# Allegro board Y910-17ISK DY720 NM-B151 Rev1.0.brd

Outline 312 x 206.5 mm; copper layers: TOP, GND02, IN03, GND04, IN05, VCC06, VCC07, IN08, GND09, IN10, GND11, BOTTOM. Coordinates in mm from the lower left corner of the outline.
Outline path: 8.78,91.9 15,91.9 arc(18.3,88.6) 15,85.3 8.78,85.3 arc(5.48,88.6) 8.78,91.9 ; 129.73,82.69 129.73,82.68 129.75,82.68 arc(129.88,82.67) 130,82.68 131.42,82.68 arc(132.06,82.87) 132.34,83.47 arc(132.1,84.05) 131.52,84.27 129.91,84.27 arc(129.08,83.56) 129.73,82.69 ; 130.17,69.48 arc(129.28,70.24) 130.1,71.07 131.74,71.07 arc(132.33,70.85) 132.57,70.27 arc(132.31,69.68) 131.68,69.48 130.17,69.48

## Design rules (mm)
constraint set DEFAULT: min track width 0.097
net group 1.05G_FB: nets 1.05G_FB N33525142
net group 1.05VP_FB: nets 1.05VP_FB N23054269
net group 2.5VP_FB: nets 2.5VP_FB N20137254
net group +V_CPU_VREF_CA: nets +V_CPU_VREF_CA N19687681
net group +V_CPU_VREF_DQ_CHB: nets +V_CPU_VREF_DQ_CHB N19686618
net group AMP_SPK_L+: nets AMP_SPK_L+ N17011867
net group CHG_TGR: nets CHG_TGR N28554284
net group CK_CPU_24M_: nets CK_CPU_24M_N CK_CPU_24M_P
net group CK_CPU_BCLK_: nets CK_CPU_BCLK_N CK_CPU_BCLK_P
net group CK_CPU_PCIBCLK_: nets CK_CPU_PCIBCLK_N CK_CPU_PCIBCLK_P
net group CK_CR_: nets CK_CR_N CK_CR_P
net group CK_LAN: nets N16819243 N16819245
net group CK_LAN_: nets CK_LAN_N CK_LAN_P
net group CK_PCIE_SSD1_: nets CK_PCIE_SSD1_N CK_PCIE_SSD1_P
net group CK_PCIE_SSD2_: nets CK_PCIE_SSD2_N CK_PCIE_SSD2_P
net group CK_PEG1_: nets CK_PEG1_N CK_PEG1_P
net group CK_TBT: nets CK_TBT_N CK_TBT_P
net group CK_WLAN_: nets CK_WLAN_N CK_WLAN_P
net group CK_XDP_: nets CK_XDP_N CK_XDP_P
net group CSCOMP_1PH_A: nets CSCOMP_1PH_A CSSUM_1PH
net group CSCOMP_3PH_A: nets CSCOMP_3PH_A CSSUM_3PH_A
net group CSN1_3PH_A: nets CSN1_3PH_A CSP1_3PH_A
net group CSN2_3PH_A: nets CSN2_3PH_A CSP2_3PH_A
net group CSN3_3PH_A: nets CSN3_3PH_A CSP3_3PH_A
net group CSN4_3PH_A: nets CSN4_3PH_A CSP4_3PH_A
net group CSN_1PH: nets CSN_1PH CSP_1PH
net group DDI1_AUX_D: nets DDI1_AUX_DN DDI1_AUX_DP
net group DDI1_AUX_OUT_D: nets DDI1_AUX_OUT_DN DDI1_AUX_OUT_DP
net group DDI1_DN0: nets DDI1_DN0 N16691099
net group DDI1_DN1: nets DDI1_DN1 N16691187
net group DDI1_DN2: nets DDI1_DN2 N16691301
net group DDI1_DN3: nets DDI1_DN3 N16691365
net group DDI1_DP0: nets DDI1_DP0 N16691093
net group DDI1_DP1: nets DDI1_DP1 N16691181
net group DDI1_DP2: nets DDI1_DP2 N16691295
net group DDI1_DP3: nets DDI1_DP3 N16691335
net group DDI2_AUX_OUT_D: nets DDI2_AUX_OUT_DN DDI2_AUX_OUT_DP
net group DDI2_DN0: nets DDI2_DN0 N16694179
net group DDI2_DN1: nets DDI2_DN1 N16694223
net group DDI2_DN2: nets DDI2_DN2 N16694291
net group DDI2_DN3: nets DDI2_DN3 N16694359
net group DDI2_DP0: nets DDI2_DP0 N16694173
net group DDI2_DP1: nets DDI2_DP1 N16694217
net group DDI2_DP2: nets DDI2_DP2 N16694285
net group DDI2_DP3: nets DDI2_DP3 N16694353
net group DDI_AUX: nets DDI2_AUX_DN DDI2_AUX_DP
net group DIFFPAIR25: nets N16694397 N16694403
net group DIFFPAIR26: nets N35290569 N35290577
net group DIFFPAIR27: nets N35290550 N35290561
net group DIFFPAIR28: nets N34625001 N34625004
net group DMI_IT_MR_0_D: nets DMI_IT_MR_0_DN DMI_IT_MR_0_DP
net group DMI_IT_MR_1_D: nets DMI_IT_MR_1_DN DMI_IT_MR_1_DP
net group DMI_IT_MR_2_D: nets DMI_IT_MR_2_DN DMI_IT_MR_2_DP
net group DMI_IT_MR_3_D: nets DMI_IT_MR_3_DN DMI_IT_MR_3_DP
net group DMI_MT_IR_0_D: nets DMI_MT_IR_0_DN DMI_MT_IR_0_DP
net group DMI_MT_IR_1_D: nets DMI_MT_IR_1_DN DMI_MT_IR_1_DP
net group DMI_MT_IR_2_D: nets DMI_MT_IR_2_DN DMI_MT_IR_2_DP
net group DMI_MT_IR_3_D: nets DMI_MT_IR_3_DN DMI_MT_IR_3_DP
net group DP_AUX_C_DP_SCL: nets DP_AUX_C_DN_SDA DP_AUX_C_DP_SCL
net group DP_AUX_OUT_DP: nets DP_AUX_OUT_DN_SDA DP_AUX_OUT_DP_SCL
net group DP_TX0_C_DN: nets DP_TX0_C_DN DP_TX0_OUT_DN
net group DP_TX0_C_DP: nets DP_TX0_C_DP DP_TX0_OUT_DP
net group DP_TX1_C_DN: nets DP_TX1_C_DN DP_TX1_OUT_DN
net group DP_TX1_C_DP: nets DP_TX1_C_DP DP_TX1_OUT_DP
net group DP_TX2_C_DN: nets DP_TX2_C_DN DP_TX2_OUT_DN
net group DP_TX2_C_DP: nets DP_TX2_C_DP DP_TX2_OUT_DP
net group DP_TX3_C_DN: nets DP_TX3_C_DN DP_TX3_OUT_DN
net group DP_TX3_C_DP: nets DP_TX3_C_DP DP_TX3_OUT_DP
net group DPA_AUX_DN_C: nets DPA_AUX_DN_C GPU_DPA_AUX_DN_SDA
net group DPA_AUX_DP_C: nets DPA_AUX_DP_C GPU_DPA_AUX_DP_SCL
net group DPA_TX0_DN_C: nets DPA_TX0_DN_C GPU_DPA_TX0_DN
net group DPA_TX0_DP_C: nets DPA_TX0_DP_C GPU_DPA_TX0_DP
net group DPA_TX1_DN_C: nets DPA_TX1_DN_C GPU_DPA_TX1_DN
net group DPA_TX1_DP_C: nets DPA_TX1_DP_C GPU_DPA_TX1_DP
net group DPA_TX2_DN_C: nets DPA_TX2_DN_C GPU_DPA_TX2_DN
net group DPA_TX2_DP_C: nets DPA_TX2_DP_C GPU_DPA_TX2_DP
net group DPA_TX3_DN_C: nets DPA_TX3_DN_C GPU_DPA_TX3_DN
net group DPA_TX3_DP_C: nets DPA_TX3_DP_C GPU_DPA_TX3_DP
net group DPE_AUX_D_C: nets DPE_AUX_DN_C DPE_AUX_DP_C
net group DPE_TX0_D_C: nets DPE_TX0_DN_C DPE_TX0_DP_C
net group DPE_TX1_D_C: nets DPE_TX1_DN_C DPE_TX1_DP_C
net group DPE_TX2_D_C: nets DPE_TX2_DN_C DPE_TX2_DP_C
net group DPE_TX3_D_C: nets DPE_TX3_DN_C DPE_TX3_DP_C
net group DPF_AUX_D_C: nets DPF_AUX_DN_C DPF_AUX_DP_C
net group DPF_TX0_D_C: nets DPF_TX0_DN_C DPF_TX0_DP_C
net group DPF_TX1_D_C: nets DPF_TX1_DN_C DPF_TX1_DP_C
net group DPF_TX2_D_C: nets DPF_TX2_DN_C DPF_TX2_DP_C
net group DPF_TX3_D_C: nets DPF_TX3_DN_C DPF_TX3_DP_C
net group EDP_AUX_C_DN: nets EDP_AUX_C_DN GPU_EDP_AUX_DN
net group EDP_AUX_C_DP: nets EDP_AUX_C_DP GPU_EDP_AUX_DP
net group EDP_TX0_C_DN: nets EDP_TX0_C_DN GPU_EDP_TX0_DN
net group EDP_TX0_C_DP: nets EDP_TX0_C_DP GPU_EDP_TX0_DP
net group EDP_TX1_C_DN: nets EDP_TX1_C_DN GPU_EDP_TX1_DN
net group EDP_TX1_C_DP: nets EDP_TX1_C_DP GPU_EDP_TX1_DP
net group FBA_CLK: nets CLKA0_N CLKA1_N
net group FBC_CLK: nets CLKC0 CLKC0_N
net group FBD_WCK: nets FBD_WCK23 FBD_WCK23_N
net group GPU_DPA_SCL: nets GPU_DPA_SCL GPU_DPA_SDA
net group GPU_DPE_AUX_DN_SDA-SCL: nets GPU_DPE_AUX_DN_SDA GPU_DPE_AUX_DP_SCL
net group GPU_DPE_TX1: nets GPU_DPE_TX1_DN GPU_DPE_TX1_DP
net group GPU_DPE_TX2: nets GPU_DPE_TX2_DN GPU_DPE_TX2_DP
net group GPU_DPE_TX3: nets GPU_DPE_TX3_DN GPU_DPE_TX3_DP
net group GPU_DPF_AUX: nets GPU_DPF_AUX_DN GPU_DPF_AUX_DP
net group GPU_DPF_TX0: nets GPU_DPF_TX0_DN GPU_DPF_TX0_DP
net group GPU_DPF_TX1: nets GPU_DPF_TX1_DN GPU_DPF_TX1_DP
net group GPU_DPF_TX2: nets GPU_DPF_TX2_DN GPU_DPF_TX2_DP
net group GPU_DPF_TX3: nets GPU_DPF_TX3_DN GPU_DPF_TX3_DP
net group GPU_HDMI_CLK_DN: nets GPU_HDMI_CLK_DN N36820474
net group GPU_HDMI_CLK_DP: nets GPU_HDMI_CLK_DP N36820476
net group GPU_HDMI_DATA0_DN: nets GPU_HDMI_DATA0_DN N36820470
net group GPU_HDMI_DATA0_DP: nets GPU_HDMI_DATA0_DP N36820472
net group GPU_HDMI_DATA1_DN: nets GPU_HDMI_DATA1_DN N36820468
net group GPU_HDMI_DATA1_DP: nets GPU_HDMI_DATA1_DP N36820466
net group GPU_HDMI_DATA2_DN: nets GPU_HDMI_DATA2_DN N36820462
net group GPU_HDMI_DATA2_DP: nets GPU_HDMI_DATA2_DP N36820464
net group GPU_HDMI_DDC_CLK: nets GPU_HDMI_DDC_CLK GPU_HDMI_DDC_DATA
net group HDMI_CLK_D: nets HDMI_CLK_DN HDMI_CLK_DP
net group HDMI_CLK_R_D: nets HDMI_CLK_R_DN HDMI_CLK_R_DP
net group HDMI_CLK_RS_D: nets HDMI_CLK_RS_DN HDMI_CLK_RS_DP
net group HDMI_DATA0_D: nets HDMI_DATA0_DN HDMI_DATA0_DP
net group HDMI_DATA0_R_D: nets HDMI_DATA0_R_DN HDMI_DATA0_R_DP
net group HDMI_DATA0_RS_D: nets HDMI_DATA0_RS_DN HDMI_DATA0_RS_DP
net group HDMI_DATA1_D: nets HDMI_DATA1_DN HDMI_DATA1_DP
net group HDMI_DATA1_R_D: nets HDMI_DATA1_R_DN HDMI_DATA1_R_DP
net group HDMI_DATA1_RS_D: nets HDMI_DATA1_RS_DN HDMI_DATA1_RS_DP
net group HDMI_DATA2_D: nets HDMI_DATA2_DN HDMI_DATA2_DP
net group HDMI_DATA2_R_D: nets HDMI_DATA2_R_DN HDMI_DATA2_R_DP
net group HDMI_DATA2_RS_D: nets HDMI_DATA2_RS_DN HDMI_DATA2_RS_DP
net group HDMI_DDC_CLK: nets HDMI_DDC_CLK HDMI_DDC_DATA
net group HDMI_DDC_CLK_R: nets HDMI_DDC_CLK_R HDMI_DDC_DATA_R
net group MDI_0: nets MDI_N0 MDI_P0
net group MDI_1: nets MDI_N1 MDI_P1
net group MDI_2: nets MDI_N2 MDI_P2
net group MDI_3: nets MDI_N3 MDI_P3
net group MDO_0: nets MDO_N0 MDO_P0
net group MDO_1: nets MDO_N1 MDO_P1
net group MDO_2: nets MDO_N2 MDO_P2
net group MDO_3: nets MDO_N3 MDO_P3
net group N16977173: nets N16977173 N16977182
net group N16977185: nets N16977185 N16977188
net group N17009645: nets N17009645 N17009647
net group N17009677: nets N17009677 N17009679
net group N17009783: nets N17009783 N17009785
net group N17791490: nets N17791490 N17791569
net group N28554029: nets N28554029 N28554039
net group N28555679: nets N28555679 N28555719
net group PC_BEEP: nets N16980185 PC_BEEP
net group PCIE1_TBT_RX_DN0: nets N16693435 PCIE1_TBT_RX_DN0
net group PCIE1_TBT_RX_DP0: nets N16693389 PCIE1_TBT_RX_DP0
net group PCIE1_TBT_TX_DN0: nets N16691949 PCIE1_TBT_TX_DN0
net group PCIE1_TBT_TX_DP0: nets N16691909 PCIE1_TBT_TX_DP0
net group PCIE2_TBT_RX_DN1: nets N16693593 PCIE2_TBT_RX_DN1
net group PCIE2_TBT_RX_DP1: nets N16693587 PCIE2_TBT_RX_DP1
net group PCIE2_TBT_TX_DN1: nets N16691945 PCIE2_TBT_TX_DN1
net group PCIE2_TBT_TX_DP1: nets N16691941 PCIE2_TBT_TX_DP1
net group PCIE3_TBT_RX_DN2: nets N16693677 PCIE3_TBT_RX_DN2
net group PCIE3_TBT_RX_DP2: nets N16693655 PCIE3_TBT_RX_DP2
net group PCIE3_TBT_TX_DN2: nets N16693835 PCIE3_TBT_TX_DN2
net group PCIE3_TBT_TX_DP2: nets N16693791 PCIE3_TBT_TX_DP2
net group PCIE4_TBT_RX_DN3: nets N16693769 PCIE4_TBT_RX_DN3
net group PCIE4_TBT_RX_DP3: nets N16693763 PCIE4_TBT_RX_DP3
net group PCIE4_TBT_TX_DN3: nets N16693831 PCIE4_TBT_TX_DN3
net group PCIE4_TBT_TX_DP3: nets N16693827 PCIE4_TBT_TX_DP3
net group PCIE9_SSD2_RX_D0: nets PCIE9_SSD2_RX_DN0 PCIE9_SSD2_RX_DP0
net group PCIE9_SSD2_RX_R_D0: nets PCIE9_SSD2_RX_R_DN0 PCIE9_SSD2_RX_R_DP0
net group PCIE9_SSD2_TX_DN0: nets PCIE9_SSD2_TX_C_DN0 PCIE9_SSD2_TX_DN0
net group PCIE9_SSD2_TX_DP0: nets PCIE9_SSD2_TX_C_DP0 PCIE9_SSD2_TX_DP0
net group PCIE10_SSD2_RX_D1: nets PCIE10_SSD2_RX_DN1 PCIE10_SSD2_RX_DP1
net group PCIE10_SSD2_TX_DN1: nets PCIE10_SSD2_TX_C_DN1 PCIE10_SSD2_TX_DN1
net group PCIE10_SSD2_TX_DP1: nets PCIE10_SSD2_TX_C_DP1 PCIE10_SSD2_TX_DP1
net group PCIE11_SSD2_RX_D2: nets PCIE11_SSD2_RX_DN2 PCIE11_SSD2_RX_DP2
net group PCIE11_SSD2_TX_DN2: nets PCIE11_SSD2_TX_C_DN2 PCIE11_SSD2_TX_DN2
net group PCIE11_SSD2_TX_DP2: nets PCIE11_SSD2_TX_C_DP2 PCIE11_SSD2_TX_DP2
net group PCIE12_SSD2_RX_D3: nets PCIE12_SSD2_RX_DN3 PCIE12_SSD2_RX_DP3
net group PCIE12_SSD2_TX_DN3: nets PCIE12_SSD2_TX_C_DN3 PCIE12_SSD2_TX_DN3
net group PCIE12_SSD2_TX_DP3: nets PCIE12_SSD2_TX_C_DP3 PCIE12_SSD2_TX_DP3
net group PCIE13_SSD1_RX_D0: nets PCIE13_SSD1_RX_DN0 PCIE13_SSD1_RX_DP0
net group PCIE13_SSD1_TX_C_DN0: nets PCIE13_SSD1_TX_C_DN0 PCIE13_SSD1_TX_DN0
net group PCIE13_SSD1_TX_C_DP0: nets PCIE13_SSD1_TX_C_DP0 PCIE13_SSD1_TX_DP0
net group PCIE14_SSD1_RX_D1: nets PCIE14_SSD1_RX_DN1 PCIE14_SSD1_RX_DP1
net group PCIE14_SSD1_TX_C_DN1: nets PCIE14_SSD1_TX_C_DN1 PCIE14_SSD1_TX_DN1
net group PCIE14_SSD1_TX_C_DP1: nets PCIE14_SSD1_TX_C_DP1 PCIE14_SSD1_TX_DP1
net group PCIE15_SSD1_RX_D2: nets PCIE15_SSD1_RX_DN2 PCIE15_SSD1_RX_DP2
net group PCIE15_SSD1_TX_C_DN2: nets PCIE15_SSD1_TX_C_DN2 PCIE15_SSD1_TX_DN2
net group PCIE15_SSD1_TX_C_DP2: nets PCIE15_SSD1_TX_C_DP2 PCIE15_SSD1_TX_DP2
net group PCIE16_SSD1_RX_D3: nets PCIE16_SSD1_RX_DN3 PCIE16_SSD1_RX_DP3
net group PCIE16_SSD1_TX_C_DN3: nets PCIE16_SSD1_TX_C_DN3 PCIE16_SSD1_TX_DN3
net group PCIE16_SSD1_TX_C_DP3: nets PCIE16_SSD1_TX_C_DP3 PCIE16_SSD1_TX_DP3
net group PCIE_CR_RX_D: nets PCIE_CR_RX_DN PCIE_CR_RX_DP
net group PCIE_CR_TX_C_DN: nets PCIE_CR_TX_C_DN PCIE_CR_TX_DN
net group PCIE_CR_TX_C_DP: nets PCIE_CR_TX_C_DP PCIE_CR_TX_DP
net group PCIE_LAN_RX_C_DN: nets PCIE_LAN_RX_C_DN PCIE_LAN_RX_DN
net group PCIE_LAN_RX_C_DP: nets PCIE_LAN_RX_C_DP PCIE_LAN_RX_DP
net group PCIE_LAN_TX_C_DN: nets PCIE_LAN_TX_C_DN PCIE_LAN_TX_DN
net group PCIE_LAN_TX_C_DP: nets PCIE_LAN_TX_C_DP PCIE_LAN_TX_DP
net group PCIE_WLAN_RX_D: nets PCIE_WLAN_RX_DN PCIE_WLAN_RX_DP
net group PCIE_WLAN_TX_C_DN: nets PCIE_WLAN_TX_C_DN PCIE_WLAN_TX_DN
net group PCIE_WLAN_TX_C_DP: nets PCIE_WLAN_TX_C_DP PCIE_WLAN_TX_DP
net group PEG_PRX_C_GTX: nets PEG_PRX_C_GTX_N12 PEG_PRX_C_GTX_P12
net group PEG_PRX_C_GTX_N0: nets PEG_PRX_C_GTX_N0 PEG_PRX_GTX_N0
net group PEG_PRX_C_GTX_N1: nets PEG_PRX_C_GTX_N1 PEG_PRX_GTX_N1
net group PEG_PRX_C_GTX_N2: nets PEG_PRX_C_GTX_N2 PEG_PRX_GTX_N2
net group PEG_PRX_C_GTX_N3: nets PEG_PRX_C_GTX_N3 PEG_PRX_GTX_N3
net group PEG_PRX_C_GTX_N4: nets PEG_PRX_C_GTX_N4 PEG_PRX_GTX_N4
net group PEG_PRX_C_GTX_N5: nets PEG_PRX_C_GTX_N5 PEG_PRX_GTX_N5
net group PEG_PRX_C_GTX_N6: nets PEG_PRX_C_GTX_N6 PEG_PRX_GTX_N6
net group PEG_PRX_C_GTX_N7: nets PEG_PRX_C_GTX_N7 PEG_PRX_GTX_N7
net group PEG_PRX_C_GTX_P0: nets PEG_PRX_C_GTX_P0 PEG_PRX_GTX_P0
net group PEG_PRX_C_GTX_P1: nets PEG_PRX_C_GTX_P1 PEG_PRX_GTX_P1
net group PEG_PRX_C_GTX_P2: nets PEG_PRX_C_GTX_P2 PEG_PRX_GTX_P2
net group PEG_PRX_C_GTX_P3: nets PEG_PRX_C_GTX_P3 PEG_PRX_GTX_P3
net group PEG_PRX_C_GTX_P4: nets PEG_PRX_C_GTX_P4 PEG_PRX_GTX_P4
net group PEG_PRX_C_GTX_P5: nets PEG_PRX_C_GTX_P5 PEG_PRX_GTX_P5
net group PEG_PRX_C_GTX_P6: nets PEG_PRX_C_GTX_P6 PEG_PRX_GTX_P6
net group PEG_PRX_C_GTX_P7: nets PEG_PRX_C_GTX_P7 PEG_PRX_GTX_P7
net group PEG_PTX_C_GRX_N0: nets PEG_PTX_C_GRX_N0 PEG_PTX_GRX_N0
net group PEG_PTX_C_GRX_N1: nets PEG_PTX_C_GRX_N1 PEG_PTX_GRX_N1
net group PEG_PTX_C_GRX_N2: nets PEG_PTX_C_GRX_N2 PEG_PTX_GRX_N2
net group PEG_PTX_C_GRX_N3: nets PEG_PTX_C_GRX_N3 PEG_PTX_GRX_N3
net group PEG_PTX_C_GRX_N4: nets PEG_PTX_C_GRX_N4 PEG_PTX_GRX_N4
net group PEG_PTX_C_GRX_N5: nets PEG_PTX_C_GRX_N5 PEG_PTX_GRX_N5
net group PEG_PTX_C_GRX_N6: nets PEG_PTX_C_GRX_N6 PEG_PTX_GRX_N6
net group PEG_PTX_C_GRX_N7: nets PEG_PTX_C_GRX_N7 PEG_PTX_GRX_N7
net group PEG_PTX_C_GRX_N8: nets PEG_PTX_C_GRX_N8 PEG_PTX_GRX_N8
net group PEG_PTX_C_GRX_N9: nets PEG_PTX_C_GRX_N9 PEG_PTX_GRX_N9
net group PEG_PTX_C_GRX_N10: nets PEG_PTX_C_GRX_N10 PEG_PTX_GRX_N10
net group PEG_PTX_C_GRX_N11: nets PEG_PTX_C_GRX_N11 PEG_PTX_GRX_N11
net group PEG_PTX_C_GRX_N12: nets PEG_PTX_C_GRX_N12 PEG_PTX_GRX_N12
net group PEG_PTX_C_GRX_N13: nets PEG_PTX_C_GRX_N13 PEG_PTX_GRX_N13
net group PEG_PTX_C_GRX_N14: nets PEG_PTX_C_GRX_N14 PEG_PTX_GRX_N14
net group PEG_PTX_C_GRX_N15: nets PEG_PTX_C_GRX_N15 PEG_PTX_GRX_N15
net group PEG_PTX_C_GRX_P0: nets PEG_PTX_C_GRX_P0 PEG_PTX_GRX_P0
net group PEG_PTX_C_GRX_P1: nets PEG_PTX_C_GRX_P1 PEG_PTX_GRX_P1
net group PEG_PTX_C_GRX_P2: nets PEG_PTX_C_GRX_P2 PEG_PTX_GRX_P2
net group PEG_PTX_C_GRX_P3: nets PEG_PTX_C_GRX_P3 PEG_PTX_GRX_P3
net group PEG_PTX_C_GRX_P4: nets PEG_PTX_C_GRX_P4 PEG_PTX_GRX_P4
net group PEG_PTX_C_GRX_P5: nets PEG_PTX_C_GRX_P5 PEG_PTX_GRX_P5
net group PEG_PTX_C_GRX_P6: nets PEG_PTX_C_GRX_P6 PEG_PTX_GRX_P6
net group PEG_PTX_C_GRX_P7: nets PEG_PTX_C_GRX_P7 PEG_PTX_GRX_P7
net group PEG_PTX_C_GRX_P8: nets PEG_PTX_C_GRX_P8 PEG_PTX_GRX_P8
net group PEG_PTX_C_GRX_P9: nets PEG_PTX_C_GRX_P9 PEG_PTX_GRX_P9
net group PEG_PTX_C_GRX_P10: nets PEG_PTX_C_GRX_P10 PEG_PTX_GRX_P10
net group PEG_PTX_C_GRX_P11: nets PEG_PTX_C_GRX_P11 PEG_PTX_GRX_P11
net group PEG_PTX_C_GRX_P12: nets PEG_PTX_C_GRX_P12 PEG_PTX_GRX_P12
net group PEG_PTX_C_GRX_P13: nets PEG_PTX_C_GRX_P13 PEG_PTX_GRX_P13
net group PEG_PTX_C_GRX_P14: nets PEG_PTX_C_GRX_P14 PEG_PTX_GRX_P14
net group PEG_PTX_C_GRX_P15: nets PEG_PTX_C_GRX_P15 PEG_PTX_GRX_P15
net group REMOTE1_N: nets REMOTE1_N REMOTE1_P
net group REMOTE2_N: nets REMOTE2_N REMOTE2_P
net group SATA_RX__R_0: nets SATA_RX__R_N0 SATA_RX__R_P0
net group SATA_RX_C_DN0: nets SATA_RX_C_DN0 SATA_RX_DN0
net group SATA_RX_C_DP0: nets SATA_RX_C_DP0 SATA_RX_DP0
net group SATA_RX_C_N0: nets SATA_RX_C_N0 SATA_RX_N0
net group SATA_RX_C_P0: nets SATA_RX_C_P0 SATA_RX_P0
net group SATA_TX__R_0: nets SATA_TX__R_N0 SATA_TX__R_P0
net group SATA_TX_C_DN0: nets SATA_TX_C_DN0 SATA_TX_DN0
net group SATA_TX_C_DP0: nets SATA_TX_C_DP0 SATA_TX_DP0
net group SATA_TX_C_N0: nets SATA_TX_C_N0 SATA_TX_N0
net group SATA_TX_C_P0: nets SATA_TX_C_P0 SATA_TX_P0
net group SWF_R+: nets N17740217 SWF_R+
net group SWF_R-: nets N17740396 SWF_R-
net group SWF_RINN: nets SWF_RINN SWF_RINP
net group TBTA_DPSRC_AUX_N: nets N16694693 TBTA_DPSRC_AUX_N
net group TBTA_DPSRC_AUX_P: nets N16694687 TBTA_DPSRC_AUX_P
net group TBTA_RX0: nets TBTA_RX0_N TBTA_RX0_P
net group TBTA_RX1: nets TBTA_RX1_N TBTA_RX1_P
net group TBTA_TX0_N: nets N16695201 TBTA_TX0_N
net group TBTA_TX0_P: nets N16695207 TBTA_TX0_P
net group TBTA_TX1_N: nets N16695077 TBTA_TX1_N
net group TBTA_TX1_P: nets N16695083 TBTA_TX1_P
net group TBTA_USB2_D: nets TBTA_USB2_D_N TBTA_USB2_D_P
net group TBTA_USB2_P_B: nets TBTA_USB2_N_B TBTA_USB2_P_B
net group TBTA_USB2_P_T: nets TBTA_USB2_N_T TBTA_USB2_P_T
net group TBTB_RX0: nets TBTB_RX0_N TBTB_RX0_P
net group TBTB_RX0_N: nets TBTB_RX0_N_R TBTB_RX0_P_R
net group TBTB_TX0: nets TBTB_TX0_N TBTB_TX0_P
net group TBTB_TX0_: nets TBTB_TX0_N_R TBTB_TX0_P_R
net group TBTB_USB2_D: nets TBTB_USB2_D_N TBTB_USB2_D_P
net group TBTB_USB2_D__R: nets TBTB_USB2_D_N_R TBTB_USB2_D_P_R
net group USB2_CHG_PN: nets USB2_CHG_PN_R USB2_CHG_PP_R
net group USB2_CHG_PP: nets USB2_CHG_PN USB2_CHG_PP
net group USB2_D1: nets USB2_DN1 USB2_DP1
net group USB2_D2: nets USB2_DN2 USB2_DP2
net group USB2_D4: nets USB2_DN4 USB2_DP4
net group USB2_D4_R: nets USB2_DN4_R USB2_DP4_R
net group USB2_D5: nets USB2_DN5 USB2_DP5
net group USB2_D6: nets USB2_DN6 USB2_DP6
net group USB3_RX_D1: nets USB3_RX_DN1 USB3_RX_DP1
net group USB3_RX_D3: nets USB3_RX_DN3 USB3_RX_DP3
net group USB3_RX_D3_R: nets USB3_RX_DN3_R USB3_RX_DP3_R
net group USB3_RX_D6: nets USB3_RX_DN6 USB3_RX_DP6
net group USB3_TX_D1: nets USB3_TX_DN1 USB3_TX_DP1
net group USB3_TX_D3: nets USB3_TX_DN3 USB3_TX_DP3
net group USB3_TX_D3_C: nets USB3_TX_DN3_C USB3_TX_DP3_C
net group USB3_TX_D3_R: nets USB3_TX_DN3_R USB3_TX_DP3_R
net group USB3_TX_D6: nets USB3_TX_DN6 USB3_TX_DP6
net group USB3_TX_D6_C: nets USB3_TX_DN6_C USB3_TX_DP6_C
net group 8: nets HDA_SPKR HDA_SYNC SERIRQ
net group 10: nets SPK_L+ SPK_L- SPK_R+ SPK_R-
net group 15: nets DMIC_DATA H_PM_SYNC PCH_JTAG_TCK PCH_JTAG_TMS SUSCLK
net group 18: nets H_PECI
net group 20: nets DMIC_CLK DMIC_CLK_R HP_OUTL HP_OUTR
net group +3VLP_EC_AVCC: nets +3VLP_EC_AVCC
net group ADIN_1: nets N28551818
net group AMP_SPK_L-: nets AMP_SPK_L-
net group AMP_SPK_R+: nets N17011679
net group DP1: nets FBB_WCK01
net group DP2: nets CLKA0
net group DP3: nets CLKA1
net group DP11: nets FBB_WCK45
net group DP12: nets FBB_WCK67
net group DP21: nets FBA_WCK01
net group DP22: nets FBA_WCK23
net group DP24: nets FBA_WCK67
net group FBA_CMD: nets CMDA0 CMDA1 CMDA2 CMDA3 CMDA4 CMDA5 CMDA6 CMDA7 CMDA8 CMDA9 CMDA10 CMDA11 CMDA12 CMDA13 CMDA14 CMDA15 CMDA16 CMDA17 CMDA18 CMDA19 CMDA20 CMDA21 CMDA22 CMDA23 CMDA24 CMDA25 CMDA26 CMDA27 CMDA28 CMDA29 CMDA30 CMDA31
net group FBA_D0: nets DQMA0 DQSA0 MDA0 MDA1 MDA2 MDA3 MDA4 MDA5 MDA6 MDA7
net group FBA_D1: nets DQMA1 DQSA1 MDA8 MDA9 MDA10 MDA11 MDA12 MDA13 MDA14 MDA15
net group FBA_D2: nets DQMA2 DQSA2 MDA16 MDA17 MDA18 MDA19 MDA20 MDA21 MDA22 MDA23
net group FBA_D3: nets DQMA3 DQSA3 MDA24 MDA25 MDA26 MDA27 MDA28 MDA29 MDA30 MDA31
net group FBA_D4: nets DQMA4 DQSA4 MDA32 MDA33 MDA34 MDA35 MDA36 MDA37 MDA38 MDA39
net group FBA_D5: nets DQMA5 DQSA5 MDA40 MDA41 MDA42 MDA43 MDA44 MDA45 MDA46 MDA47
net group FBA_D6: nets DQMA6 DQSA6 MDA48 MDA49 MDA50 MDA51 MDA52 MDA53 MDA54 MDA55
net group FBA_D7: nets DQMA7 DQSA7 MDA56 MDA57 MDA58 MDA59 MDA60 MDA61 MDA62 MDA63
net group FBA_WCK: nets FBA_WCK01_N FBA_WCK23_N FBA_WCK67_N
net group FBB_CLK: nets CLKB0 CLKB0_N CLKB1 CLKB1_N
net group FBB_CMD: nets CMDB0 CMDB1 CMDB2 CMDB3 CMDB4 CMDB5 CMDB6 CMDB7 CMDB8 CMDB9 CMDB10 CMDB11 CMDB12 CMDB13 CMDB14 CMDB15 CMDB16 CMDB17 CMDB18 CMDB19 CMDB20 CMDB21 CMDB22 CMDB23 CMDB24 CMDB25 CMDB26 CMDB27 CMDB28 CMDB29 CMDB30 CMDB31
net group FBB_D0: nets DQMB0 DQSB0 MDB0 MDB1 MDB2 MDB3 MDB4 MDB5 MDB6 MDB7
net group FBB_D1: nets DQMB1 DQSB1 MDB8 MDB9 MDB10 MDB11 MDB12 MDB13 MDB14 MDB15
net group FBB_D2: nets DQMB2 DQSB2 MDB16 MDB17 MDB18 MDB19 MDB20 MDB21 MDB22 MDB23
net group FBB_D3: nets DQMB3 DQSB3 MDB24 MDB25 MDB26 MDB27 MDB28 MDB29 MDB30 MDB31
net group FBB_D4: nets DQMB4 DQSB4 MDB32 MDB33 MDB34 MDB35 MDB36 MDB37 MDB38 MDB39
net group FBB_D5: nets DQMB5 DQSB5 MDB40 MDB41 MDB42 MDB43 MDB44 MDB45 MDB46 MDB47
net group FBB_D6: nets DQMB6 DQSB6 MDB48 MDB49 MDB50 MDB51 MDB52 MDB53 MDB54 MDB55
net group FBB_D7: nets DQMB7 DQSB7 MDB56 MDB57 MDB58 MDB59 MDB60 MDB61 MDB62 MDB63
net group FBB_WCK: nets FBB_WCK01_N FBB_WCK45_N FBB_WCK67_N
net group FBC_CMD: nets CMDC0 CMDC1 CMDC2 CMDC3 CMDC4 CMDC5 CMDC6 CMDC7 CMDC8 CMDC9 CMDC10 CMDC11 CMDC12 CMDC13 CMDC14 CMDC15 CMDC16 CMDC17 CMDC18 CMDC19 CMDC20 CMDC21 CMDC22 CMDC23 CMDC24 CMDC25 CMDC26 CMDC27 CMDC28 CMDC29 CMDC30 CMDC31
net group FBC_D0: nets DQMC0 DQSC0 MDC0 MDC1 MDC2 MDC3 MDC4 MDC5 MDC6 MDC7
net group FBC_D1: nets DQMC1 DQSC1 MDC8 MDC9 MDC10 MDC11 MDC12 MDC13 MDC14 MDC15
net group FBC_D2: nets DQMC2 DQSC2 MDC16 MDC17 MDC18 MDC19 MDC20 MDC21 MDC22 MDC23
net group FBC_D3: nets DQMC3 DQSC3 MDC24 MDC25 MDC26 MDC27 MDC28 MDC29 MDC30 MDC31
net group FBC_D4: nets DQMC4 DQSC4 MDC32 MDC33 MDC34 MDC35 MDC36 MDC37 MDC38 MDC39
net group FBC_D5: nets DQMC5 DQSC5 MDC40 MDC41 MDC42 MDC43 MDC44 MDC45 MDC46 MDC47
net group FBC_D6: nets DQMC6 DQSC6 MDC48 MDC49 MDC50 MDC51 MDC52 MDC53 MDC54 MDC55
net group FBC_D7: nets DQMC7 DQSC7 MDC56 MDC57 MDC58 MDC59 MDC60 MDC61 MDC62 MDC63
net group FBC_WCK: nets FBC_WCK01 FBC_WCK01_N FBC_WCK23 FBC_WCK23_N FBC_WCK67 FBC_WCK67_N
net group FBD_CLK: nets CLKD0 CLKD0_N CLKD1 CLKD1_N
net group FBD_CMD: nets CMDD0 CMDD1 CMDD2 CMDD3 CMDD4 CMDD5 CMDD6 CMDD7 CMDD8 CMDD9 CMDD10 CMDD11 CMDD12 CMDD13 CMDD14 CMDD15 CMDD16 CMDD17 CMDD18 CMDD19 CMDD20 CMDD21 CMDD22 CMDD23 CMDD24 CMDD25 CMDD26 CMDD27 CMDD28 CMDD29 CMDD30 CMDD31
net group FBD_D0: nets DQMD0 DQSD0 MDD0 MDD1 MDD2 MDD3 MDD4 MDD5 MDD6 MDD7
net group FBD_D1: nets DQMD1 DQSD1 MDD8 MDD9 MDD10 MDD11 MDD12 MDD13 MDD14 MDD15
net group FBD_D2: nets DQMD2 DQSD2 MDD16 MDD17 MDD18 MDD19 MDD20 MDD21 MDD22 MDD23
net group FBD_D3: nets DQMD3 DQSD3 MDD24 MDD25 MDD26 MDD27 MDD28 MDD29 MDD30 MDD31
net group FBD_D4: nets DQMD4 DQSD4 MDD32 MDD33 MDD34 MDD35 MDD36 MDD37 MDD38 MDD39
net group FBD_D5: nets DQMD5 DQSD5 MDD40 MDD41 MDD42 MDD43 MDD44 MDD45 MDD46 MDD47
net group FBD_D6: nets DQMD6 DQSD6 MDD48 MDD49 MDD50 MDD51 MDD52 MDD53 MDD54 MDD55
net group FBD_D7: nets DQMD7 DQSD7 MDD56 MDD57 MDD58 MDD59 MDD60 MDD61 MDD62 MDD63
net group GPU_DPE_TX0: nets GPU_DPE_TX0_DN
net group N18288662: nets N18288662
net group NEAR TO PEG: nets +1.0V_VCCST_VCCSFR +1.0VALW +VCCSFR_OC DGPU_PEX_RST_N DGPU_PWROK GPU_DPE_TX0_DP GPU_EDP_BL_PWM_R H_THRMTRIP_N H_VCCST_PWRGD MAINON SUSON USB2_DN3
net group PEG: nets PEG_PRX_C_GTX_N8 PEG_PRX_C_GTX_N9 PEG_PRX_C_GTX_N10 PEG_PRX_C_GTX_N11 PEG_PRX_C_GTX_N13 PEG_PRX_C_GTX_N14 PEG_PRX_C_GTX_N15 PEG_PRX_C_GTX_P8 PEG_PRX_C_GTX_P9 PEG_PRX_C_GTX_P10 PEG_PRX_C_GTX_P11 PEG_PRX_C_GTX_P13 PEG_PRX_C_GTX_P14 PEG_PRX_C_GTX_P15 PEG_PRX_GTX_N8 PEG_PRX_GTX_N9 PEG_PRX_GTX_N10 PEG_PRX_GTX_N11 PEG_PRX_GTX_N12 PEG_PRX_GTX_N13 PEG_PRX_GTX_N14 PEG_PRX_GTX_N15 PEG_PRX_GTX_P8 PEG_PRX_GTX_P9 PEG_PRX_GTX_P10 PEG_PRX_GTX_P11 PEG_PRX_GTX_P12 PEG_PRX_GTX_P13 PEG_PRX_GTX_P14 PEG_PRX_GTX_P15
net group POWER: nets +3VALWP
net group PWR: nets +1.0V_VCCSFR +1.0V_VCCSTG_RC +1.2V_BST +1.2V_FB +1.2V_LG +1.2V_TON +1.2V_UGR +1.2VDDQ +1.05V_DGPU_PGOOD +1.8VA_AUD +1.8VALW_PCH +3V_1.8V_EC +3VA_AMP +3VALW_EC_FSPI +3VALW_LC_SPI +3VALW_SLG +3VALW_SPI +5V_KB_LED +5V_USB_KB +5VLDO +12V_SWF_BOOST +RTC_VCC +V3.3A_VCCPAZIO +V3.3A_VCCPGPPEF +V3.3A_VCCPGPPG +V3.3S_VCCATS +V_CPU_VREF_DQ_CHA +V_DIM_VREF_CA_CHA +V_DIM_VREF_CA_CHB +VBAT_EC +VCCAPLLEBB_1P0 +VCCAUSB_1P0_L +VCCDTS_1P0 +VCCDUSB_1P0 +VCCF100OC_1P0 +VCCFHV_2P8 +VCCPRTCPRIM_3P3 +VCCVDDQ_CLK +VSTBY0_EC +VTT_REFP
net group USB2_D3: nets USB2_DP3
net group XDP: nets XDP_TDI XDP_TDO XDP_TMS
nets with their own width: min track width 0.254; nets +1.8V_AON +1.8V_MAIN +1.55VSG +3V +CORE_PLLVDD_GPU +FB_PLL_AVDD +IFP_IOVDD +IFPAB_PLLVDD +IFPCD_PLLVDD +IFPEF_PLLVDD +PEX_VDD +VID_PLLVDD_GPU_1 +VID_PLLVDD_GPU_2 CFG_RCOMP FB_REFPLL_AVDD_GPU GND VDD18_GPU
nets with their own width: min track width 0.305; nets PEG_RCOMP
nets with their own width: min track width 0.381; nets +5VALW +NVVDDS +VGA_CORE
nets with their own width: min track width 1.016; nets CHASSIS1_GND
nets with their own width: min track width 1.524; nets B+

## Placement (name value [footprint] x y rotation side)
C1  -  [C_0402NEW]  199.56 154.51 180 bottom
C2  -  [C_0402NEW]  199.56 153.62 180 bottom
C3  -  [C_0402NEW]  197.58 151.97 180 bottom
C4  -  [C_0402NEW]  197.58 152.86 180 bottom
C5  -  [C_0402NEW]  199.44 150.45 180 bottom
C6  -  [C_0402NEW]  199.44 151.34 180 bottom
C7  -  [C_0402NEW]  202.99 149.05 180 bottom
C8  -  [C_0402NEW]  202.99 149.94 180 bottom
C9  -  [C_0402NEW]  199.49 148.03 180 bottom
C10  -  [C_0402NEW]  199.49 148.92 180 bottom
C11  -  [C_0402NEW]  202.92 147.12 180 bottom
C12  -  [C_0402NEW]  202.92 146.26 180 bottom
C13  -  [C_0402NEW]  199.49 145.62 180 bottom
C14  -  [C_0402NEW]  199.49 144.73 180 bottom
C15  -  [C_0402NEW]  202.92 142.95 180 bottom
C16  -  [C_0402NEW]  202.94 143.82 180 bottom
C17  -  [C_0402NEW]  199.44 141.68 180 bottom
C18  -  [C_0402NEW]  199.44 142.57 180 bottom
C19  -  [C_0402NEW]  202.99 140.29 180 bottom
C20  -  [C_0402NEW]  202.99 141.18 180 bottom
C21  -  [C_0402NEW]  199.44 139.27 180 bottom
C22  -  [C_0402NEW]  199.44 140.16 180 bottom
C23  -  [C_0402NEW]  202.99 137.62 180 bottom
C24  -  [C_0402NEW]  202.99 138.51 180 bottom
C25  -  [C_0402NEW]  199.44 137.62 180 bottom
C26  -  [C_0402NEW]  199.44 136.73 180 bottom
C27  -  [C_0402NEW]  202.99 134.95 180 bottom
C28  -  [C_0402NEW]  202.99 135.84 180 bottom
C29  -  [C_0402NEW]  199.44 134.19 180 bottom
C30  -  [C_0402NEW]  199.44 135.08 180 bottom
C31  -  [C_0402NEW]  202.99 132.29 180 bottom
C32  -  [C_0402NEW]  202.99 133.18 180 bottom
C33  -  [C_0402NEW]  148.69 152.43 270 top
C34  -  [C_B2]  222.83 159.46 0 top
C35  -  [C_0402NEW]  196.36 62.69 0 bottom
C36  -  [C_0402NEW]  197.28 63.58 180 bottom
C37  -  [C_0402NEW]  169.9 94.52 270 bottom
C38  -  [C_0402NEW]  167.23 93.6 90 bottom
C39  -  [C_B2]  121.23 61.67 0 top
C40  -  [C_0603NEW]  191.36 62.75 270 bottom
C41  -  [C_0603NEW]  175.86 62.75 270 bottom
C42  -  [C_0603NEW]  181.96 62.75 270 bottom
C43  -  [C_0603NEW]  168.37 62.75 270 bottom
C44  -  [C_0603NEW]  157.83 62.75 270 bottom
C45  -  [C_0603NEW]  185.01 62.75 270 bottom
C46  -  [C_0603NEW]  154.78 62.75 270 bottom
C47  -  [C_0603NEW]  166.97 62.75 270 bottom
C48  -  [C_0603NEW]  160.88 62.75 270 bottom
C49  -  [C_0603NEW]  163.93 62.75 270 bottom
C50  -  [C_0603NEW]  206.53 71.45 0 top
C51  -  [C_0603NEW]  206.53 69.17 0 top
C52  -  [C_0402NEW]  206.83 65.74 0 top
C53  -  [C_0402NEW]  206.78 77.04 0 top
C54  -  [C_0402NEW]  171.67 93.6 90 bottom
C55  -  [C_0402NEW]  150.46 62.51 270 bottom
C56  -  [C_0402NEW]  147.42 62.51 270 bottom
C57  -  [C_0402NEW]  165.7 62.51 270 bottom
C58  -  [C_0402NEW]  156.56 62.51 270 bottom
C59  -  [C_0402NEW]  162.66 62.51 270 bottom
C60  -  [C_0402NEW]  144.37 62.51 270 bottom
C61  -  [C_0402NEW]  172.82 62.51 270 bottom
C62  -  [C_0402NEW]  159.61 62.51 270 bottom
C63  -  [C_0402NEW]  153.51 62.51 270 bottom
C64  -  [C_0402NEW]  144.11 90.63 90 bottom
C65  -  [C_0603NEW]  206.66 70.44 0 bottom
C66  -  [C_0603NEW]  206.53 75.26 0 bottom
C67  -  [C_0402NEW]  206.78 76.41 0 bottom
C68  -  [C_0402NEW]  195.35 91.27 0 bottom
C69  -  [C_0402NEW]  196.26 93.04 180 bottom
C70  -  [C_0402NEW]  169.01 94.52 270 bottom
C71  -  [C_0402NEW]  31.41 44.15 180 bottom
C72  -  [C_B2]  120.98 96.85 0 top
C73  -  [C_0603NEW]  146.27 90.5 90 bottom
C74  -  [C_0603NEW]  155.42 90.38 90 bottom
C75  -  [C_0603NEW]  139.92 90.31 90 bottom
C76  -  [C_0603NEW]  174.21 91.27 90 bottom
C77  -  [C_0603NEW]  150.21 90.63 90 bottom
C78  -  [C_0603NEW]  160.24 90.44 90 bottom
C79  -  [C_0603NEW]  179.55 90.44 90 bottom
C80  -  [C_0603NEW]  185.01 90.38 90 bottom
C81  -  [C_0603NEW]  142.21 90.38 90 bottom
C82  -  [C_0603NEW]  162.53 90.5 90 bottom
C83  -  [C_0603NEW]  206.53 73.74 0 top
C84  -  [C_0603NEW]  206.53 79.2 0 top
C85  -  [C_0402NEW]  206.78 74.88 0 top
C86  -  [C_0402NEW]  206.78 72.6 0 top
C87  -  [C_B2]  231.64 161.75 180 top
C88  -  [C_0402NEW]  183.74 62.51 270 bottom
C89  -  [C_0402NEW]  177.64 62.51 270 bottom
C90  -  [C_0402NEW]  137.76 90.63 90 bottom
C91  -  [C_0402NEW]  141.07 90.63 90 bottom
C92  -  [C_0402NEW]  148.43 90.63 90 bottom
C93  -  [C_0402NEW]  195.04 62.51 270 bottom
C94  -  [C_0402NEW]  156.56 90.5 90 bottom
C95  -  [C_0402NEW]  194.15 62.51 270 bottom
C96  -  [C_0402NEW]  134.72 90.68 90 bottom
C97  -  [C_0402NEW]  138.78 90.63 90 bottom
C98  -  [C_0603NEW]  206.53 80.85 0 bottom
C99  -  [C_0603NEW]  206.53 78.34 0 bottom
C100  -  [C_0402NEW]  206.78 77.3 0 bottom
C101  -  [C_0402NEW]  196.36 60.91 0 bottom
C102  -  [C_0402NEW]  197.28 61.8 180 bottom
C103  -  [C_0402NEW]  171.67 59.72 270 bottom
C104  -  [C_0402NEW]  173.45 58.8 90 bottom
C105  -  [C_B2]  120.98 92.92 0 top
C106  -  [C_0603NEW]  164.94 90.38 90 bottom
C107  -  [C_0603NEW]  176.37 90.5 90 bottom
C108  -  [C_0603NEW]  188.44 90.38 90 bottom
C109  -  [C_0603NEW]  170.53 90.5 90 bottom
C110  -  [C_0603NEW]  136.24 90.63 90 bottom
C111  -  [C_0603NEW]  178.91 62.75 270 bottom
C112  -  [C_0603NEW]  182.34 90.25 90 bottom
C113  -  [C_0603NEW]  171.55 62.75 270 bottom
C114  -  [C_0603NEW]  192.76 90.38 90 bottom
C115  -  [C_0603NEW]  157.83 90.38 90 bottom
C116  -  [C_0603NEW]  206.53 66.88 0 top
C117  -  [C_0603NEW]  206.53 75.92 0 top
C118  -  [C_0402NEW]  206.78 68.02 0 top
C119  -  [C_0402NEW]  206.78 70.31 0 top
C120  -  [C_0402NEW]  174.34 59.72 270 bottom
C121  -  [C_0402NEW]  183.61 90.38 90 bottom
C122  -  [C_0402NEW]  186.53 90.38 90 bottom
C123  -  [C_0402NEW]  174.59 62.51 270 bottom
C124  -  [C_0402NEW]  170.4 62.51 270 bottom
C125  -  [C_0402NEW]  152.24 90.63 90 bottom
C126  -  [C_0402NEW]  167.23 90.63 90 bottom
C127  -  [C_0402NEW]  190.09 62.51 270 bottom
C128  -  [C_0402NEW]  187.04 62.51 270 bottom
C129  -  [C_0402NEW]  136.62 62.44 270 bottom
C130  -  [C_0402NEW]  139.67 62.51 270 bottom
C131  -  [C_0603NEW]  206.53 79.58 0 bottom
C132  -  [C_0603NEW]  206.53 82.12 0 bottom
C133  -  [C_0402NEW]  206.78 69.29 0 bottom
C134  -  [C_0402NEW]  195.35 90.38 0 bottom
C135  -  [C_0402NEW]  196.26 92.15 180 bottom
C136  -  [C_0402NEW]  175.23 58.8 90 bottom
C137  -  [C_0603NEW]  13.11 42.37 180 bottom
C138  -  [C_B2]  121.23 57.86 0 top
C139  -  [C_0603NEW]  141.32 62.75 270 bottom
C140  -  [C_0603NEW]  138.4 62.75 270 bottom
C141  -  [C_0603NEW]  151.73 62.75 270 bottom
C142  -  [C_0603NEW]  194.15 90.5 90 bottom
C143  -  [C_0603NEW]  188.31 62.75 270 bottom
C144  -  [C_0603NEW]  135.33 62.75 270 bottom
C145  -  [C_0603NEW]  193.01 62.75 270 bottom
C146  -  [C_0603NEW]  190.09 90.38 90 bottom
C147  -  [C_0603NEW]  145.64 62.75 270 bottom
C148  -  [C_0603NEW]  148.69 62.75 270 bottom
C149  -  [C_0603NEW]  206.53 80.47 0 top
C150  -  [C_0603NEW]  206.86 64.7 0 top
C151  -  [C_0402NEW]  206.78 81.61 0 top
C152  -  [C_0402NEW]  206.78 78.06 0 top
C153  -  [C_0805NEW]  235.94 144.73 270 top
C154  -  [C_0402NEW]  178.02 90.5 90 bottom
C155  -  [C_0402NEW]  181.07 90.38 90 bottom
C156  -  [C_0402NEW]  169.26 90.63 90 bottom
C157  -  [C_0402NEW]  171.67 90.63 90 bottom
C158  -  [C_0402NEW]  161.39 90.63 90 bottom
C159  -  [C_0402NEW]  168.24 90.63 90 bottom
C160  -  [C_0402NEW]  191.36 90.5 90 bottom
C161  -  [C_0402NEW]  163.67 90.63 90 bottom
C162  -  [C_0402NEW]  180.69 62.51 270 bottom
C163  -  [C_0402NEW]  158.97 90.63 90 bottom
C164  -  [C_0603NEW]  206.53 72.72 0 bottom
C165  -  [C_0603NEW]  206.53 73.99 0 bottom
C166  -  [C_0402NEW]  206.78 71.58 0 bottom
C167  -  [C_0805NEW]  242.79 143.75 90 top
C168  -  [C_0201NEW]  4.93 171 180 top
C169  -  [C_0201NEW]  5.67 174.35 0 top
C170  -  [C_0402NEW]  160.88 59.85 270 bottom
C171  -  [C_0402NEW]  154.02 91.52 270 bottom
C172  -  [C_0402NEW]  161.06 94.57 0 bottom
C173  -  [C_0402NEW]  170.78 93.6 90 bottom
C174  -  [C_0402NEW]  142.59 61.55 90 bottom
C175  -  [C_0402NEW]  164.61 59.01 0 bottom
C176  -  [C_0402NEW]  172.56 59.72 270 bottom
C177  -  [C_0402NEW]  217.32 58.88 0 bottom
C178  -  [C_0402NEW]  218.23 60.4 180 bottom
C179  -  [C_0402NEW]  247.57 46.69 180 top
C180  -  [C_0402NEW]  249.27 46.64 270 bottom
C181  -  [C_0402NEW]  298.11 45.42 180 bottom
C182  -  [C_0402NEW]  298.11 46.31 180 bottom
C183  -  [C_0402NEW]  271.06 80.98 180 bottom
C184  -  [C_0402NEW]  271.06 81.87 180 bottom
C185  -  [C_0402NEW]  51.81 62.92 0 top
C186  -  [C_0402NEW]  51.81 62.06 0 top
C187  -  [C_0402NEW]  242.79 48.29 270 bottom
C188  -  [C_0402NEW]  244.65 49.64 180 top
C189  -  [C_0402NEW]  108.45 52.03 0 bottom
C190  -  [C_0402NEW]  108.45 53.04 0 bottom
C191  -  [C_0402NEW]  108.45 49.49 0 bottom
C192  -  [C_0402NEW]  108.45 50.5 0 bottom
C193  -  [C_0402NEW]  108.45 46.31 0 bottom
C194  -  [C_0402NEW]  108.45 47.33 0 bottom
C195  -  [C_0402NEW]  108.45 43.77 0 bottom
C196  -  [C_0402NEW]  108.45 44.79 0 bottom
C197  -  [C_0402NEW]  107.93 76.28 0 bottom
C198  -  [C_0402NEW]  107.93 77.3 0 bottom
C199  -  [C_0402NEW]  107.74 73.87 0 bottom
C200  -  [C_0402NEW]  107.74 74.76 0 bottom
C201  -  [C_0402NEW]  107.74 70.82 0 bottom
C202  -  [C_0402NEW]  107.74 71.84 0 bottom
C203  -  [C_0402NEW]  109.32 60.73 270 bottom
C204  -  [C_0402NEW]  108.43 60.73 270 bottom
C205  -  [C_0402NEW]  245.41 45.93 180 bottom
C206  -  [C_0402NEW]  246.81 76.66 180 bottom
C207  -  [C_0402NEW]  247.67 76.66 0 bottom
C208  -  [C_0402NEW]  242.72 45.93 0 bottom
C209  -  [C_0402NEW]  235.17 51.49 90 top
C210  -  [C_0603NEW]  253.65 61.37 0 bottom
C211  -  [C_0603NEW]  253.65 63.33 0 bottom
C212  -  [C_0402NEW]  234.28 53.39 90 top
C213  -  [C_0603NEW]  249.46 70.56 180 top
C214  -  [C_0603NEW]  250.1 72.98 180 top
C215  -  [C_0402NEW]  248.84 69.42 180 top
C216  -  [C_0603NEW]  234.86 66.81 180 top
C217  -  [C_0603NEW]  228.57 75.71 270 top
C219  -  [C_0402NEW]  239.57 61.8 180 top
C220  -  [C_0402NEW]  241.73 62.69 180 top
C221  -  [C_0402NEW]  229.08 51.57 90 top
C222  -  [C_0402NEW]  243.12 60.4 180 top
C223  -  [C_0402NEW]  230.68 58.12 180 top
C224  -  [C_0402NEW]  229.66 62.69 180 top
C225  -  [C_0402NEW]  246.22 59.26 270 top
C226  -  [C_0402NEW]  237.87 52.1 270 top
C227  -  [C_0402NEW]  237.87 53.83 270 top
C228  -  [C_0402NEW]  236.75 54.69 0 top
C229  -  [C_0402NEW]  237.66 55.58 180 top
C230  -  [C_0402NEW]  32.56 55.32 180 top
C231  -  [C_0402NEW]  31.59 52.35 270 top
C232  -  [C_0402NEW]  31.59 49.66 90 top
C233  -  [C_0402NEW]  36.8 56.54 270 top
C234  -  [C_0402NEW]  32.48 52.35 270 top
C235  -  [C_0402NEW]  33.88 52.35 270 top
C236  -  [C_0402NEW]  32.48 49.66 90 top
C237  -  [C_0402NEW]  38.91 50.88 180 top
C238  -  [C_0402NEW]  31.41 45.93 180 bottom
C239  -  [C_0402NEW]  30.5 46.82 0 bottom
C240  -  [C_0805NEW]  200.92 164.16 0 bottom
C241  -  [C_0402NEW]  36.75 52.28 180 top
C242  -  [C_0402NEW]  33.88 53.22 90 top
C243  -  [C_0402NEW]  27.99 50.24 180 bottom
C244  -  [C_0402NEW]  28.62 55.2 180 bottom
C245  -  [C_0402NEW]  27.07 45.8 0 bottom
C246  -  [C_0402NEW]  37.18 44.2 90 bottom
C247  -  [C_0402NEW]  26.26 54.23 90 bottom
C248  -  [C_0402NEW]  136.93 146.76 0 bottom
C249  -  [C_0402NEW]  72.36 5.11 270 top
C250  -  [C_0603NEW]  43.66 68.98 270 bottom
C251  -  [C_0603NEW]  45.74 69.87 270 bottom
C252  -  [C_0402NEW]  49.19 67.01 180 bottom
C253  -  [C_0402NEW]  47.72 64.65 90 bottom
C254  -  [C_0402NEW]  48.61 64.65 90 bottom
C255  -  [C_0603NEW]  59.02 64.79 90 top
C256  -  [C_0402NEW]  56.99 65.69 270 top
C257  -  [C_0402NEW]  49.17 63.71 0 bottom
C258  -  [C_0402NEW]  57.88 64.77 90 top
C259  -  [C_0402NEW]  49.55 64.6 0 bottom
C260  -  [C_0402NEW]  50.52 58.58 270 top
C261  -  [C_0402NEW]  46.83 64.65 90 bottom
C262  -  [C_0402NEW]  44.88 63.58 180 bottom
C263  -  [C_0402NEW]  44.88 61.29 180 bottom
C264  -  [C_0402NEW]  44.88 60.4 180 bottom
C265  -  [C_0402NEW]  50.08 62.82 180 bottom
C266  -  [C_0402NEW]  50.08 61.04 180 bottom
C267  -  [C_0402NEW]  49.17 61.93 0 bottom
C268  -  [C_0402NEW]  41.96 65.48 180 bottom
C269  -  [C_0402NEW]  44.88 62.44 180 bottom
C270  -  [C_0402NEW]  41.04 66.5 0 bottom
C271  -  [C_0402NEW]  45.94 65.56 270 bottom
C272  -  [C_0402NEW]  45.05 64.65 90 bottom
C273  -  [C_0402NEW]  44.85 58.25 0 top
C274  -  [C_0402NEW]  47.72 57.15 90 top
C275  -  [C_0402NEW]  48.74 57.15 90 top
C276  -  [C_0402NEW]  45.89 68.15 180 top
C277  -  [C_0402NEW]  46.73 68.1 0 top
C278  -  [C_0402NEW]  4.67 115.85 270 top
C279  -  [C_0402NEW]  13.81 115.73 270 top
C280  -  [C_0402NEW]  2.51 90.3 90 top
C281  -  [C_0402NEW]  3.53 90.3 90 top
C282  -  [C_0402NEW]  31.13 100.41 0 top
C283  -  [C_0402NEW]  32.05 101.43 180 top
C284  -  [C_0402NEW]  31.13 102.44 0 top
C285  -  [C_0402NEW]  32.05 96.47 180 top
C286  -  [C_0402NEW]  31.13 98.63 0 top
C287  -  [C_0402NEW]  32.05 99.52 180 top
C288  -  [C_0402NEW]  31.13 97.36 0 top
C289  -  [C_0402NEW]  32.05 94.44 180 top
C290  -  [C_0402NEW]  31.13 93.55 0 top
C291  -  [C_1206]  19.46 106.25 180 top
C292  -  [C_0603NEW]  294.23 39.64 270 bottom
C293  -  [C_0402NEW]  295.5 38.87 90 bottom
C294  -  [C_0603NEW]  287.5 37.74 270 bottom
C295  -  [C_0402NEW]  289.02 36.58 90 bottom
C296  -  [C_0603NEW]  295.5 40.4 270 top
C297  -  [C_0402NEW]  294.36 39.25 90 top
C298  -  [C_0603NEW]  290.74 37.62 0 bottom
C299  -  [C_0402NEW]  291.84 39.14 180 bottom
C300  -  [C_0402NEW]  289.91 27.89 180 top
C301  -  [C_0402NEW]  289.91 27 180 top
C302  -  [C_0402NEW]  285.03 33.73 180 bottom
C303  -  [C_0402NEW]  285.26 27.51 0 bottom
C304  -  [C_0402NEW]  285.03 31.7 180 bottom
C305  -  [C_0402NEW]  285.03 32.72 180 bottom
C306  -  [C_0402NEW]  293.11 39.48 180 top
C307  -  [C_0402NEW]  292.19 38.61 0 top
C308  -  [C_0402NEW]  33.5 48.9 90 top
C309  -  [C_0402NEW]  291.33 38.59 90 top
C310  -  [C_0402NEW]  28.62 59.52 180 bottom
C311  -  [C_0805NEW]  200.92 162.39 0 bottom
C312  -  [C_0805NEW]  209.23 172.29 180 bottom
C313  -  [C_0402NEW]  293.09 38.61 90 bottom
C314  -  [C_0402NEW]  236.82 65.05 270 top
C315  -  [C_0402NEW]  293.64 29.42 0 top
C316  -  [C_0402NEW]  227.17 72.5 180 top
C317  -  [C_0402NEW]  293.26 28.27 0 top
C318  -  [C_0402NEW]  292.32 28.22 270 top
C319  -  [C_0603NEW]  227.17 75.71 270 top
C320  -  [C_0402NEW]  77.69 5.36 270 top
C321  -  [C_0402NEW]  291.18 28.22 270 top
C322  -  [C_0402NEW]  291.26 29.67 180 bottom
C323  -  [C_0402NEW]  290.34 28.78 0 bottom
C324  -  [C_0402NEW]  289.35 30.43 180 bottom
C325  -  [C_0402NEW]  288.44 29.54 0 bottom
C326  -  [C_0402NEW]  289.86 27.89 180 bottom
C327  -  [C_0402NEW]  289.86 27 180 bottom
C328  -  [C_0402NEW]  285.47 27.05 90 top
C329  -  [C_0402NEW]  284.58 27.05 90 top
C330  -  [C_0402NEW]  287.32 27.38 180 top
C331  -  [C_0402NEW]  286.4 26.5 0 top
C332  -  [C_0402NEW]  281.2 32.97 0 top
C333  -  [C_0402NEW]  284.12 34.75 0 bottom
C334  -  [C_0402NEW]  281.2 35.89 0 bottom
C335  -  [C_0402NEW]  281.2 36.78 0 bottom
C336  -  [C_0402NEW]  281.2 37.67 0 bottom
C337  -  [C_0402NEW]  281.2 38.56 0 bottom
C338  -  [C_0402NEW]  284.53 39.07 180 bottom
C339  -  [C_0402NEW]  284.12 30.69 0 bottom
C340  -  [C_0402NEW]  265.48 33.61 180 top
C341  -  [C_0805NEW]  274.89 37.93 180 bottom
C342  -  [C_0805NEW]  269.5 37.04 0 bottom
C343  -  [C_0805NEW]  267.8 34.95 180 bottom
C344  -  [C_0805NEW]  276.36 37.93 0 bottom
C345  -  [C_0402NEW]  266.31 34.57 180 top
C346  -  [C_0402NEW]  278.23 33.81 0 top
C347  -  [C_0603NEW]  266.22 26.62 180 bottom
C348  -  [C_0402NEW]  265.45 27.77 0 bottom
C349  -  [C_0402NEW]  265.58 30.43 0 bottom
C350  -  [C_0402NEW]  278.35 29.11 270 top
C351  -  [C_0402NEW]  266.26 36.48 270 top
C352  -  [C_0402NEW]  267.63 38.81 0 top
C353  -  [C_0402NEW]  278.23 36.45 90 top
C354  -  [C_0402NEW]  278.23 35.59 270 top
C355  -  [C_0402NEW]  296.34 62.44 180 top
C356  -  [C_0402NEW]  296.34 60.91 180 top
C357  -  [C_0402NEW]  296.34 59.9 180 top
C358  -  [C_0402NEW]  273.45 26.5 0 bottom
C359  -  [C_0402NEW]  296.34 63.45 180 top
C360  -  [C_0402NEW]  280.51 30.38 270 top
C361  -  [C_0402NEW]  279.19 31.07 180 top
C362  -  [C_0402NEW]  278.28 31.96 0 top
C363  -  [C_0402NEW]  280.05 31.96 0 top
C364  -  [C_0402NEW]  266.49 31.7 180 top
C365  -  [C_0402NEW]  265.58 30.43 0 top
C366  -  [C_0402NEW]  280.46 50.24 180 bottom
C367  -  [C_0402NEW]  286.15 44.2 270 top
C368  -  [C_0402NEW]  287.75 54.74 0 top
C369  -  [C_0805NEW]  288.42 46.43 0 top
C370  -  [C_0805NEW]  287.54 56.98 0 top
C371  -  [C_0805NEW]  288.3 54.56 0 bottom
C372  -  [C_0805NEW]  285.97 45.66 270 bottom
C373  -  [C_0402NEW]  280.46 49.36 180 bottom
C374  -  [C_0402NEW]  288.01 51.34 270 top
C375  -  [C_0402NEW]  280.46 48.47 180 bottom
C376  -  [C_0402NEW]  288.01 48.64 90 top
C377  -  [C_0402NEW]  293.09 51.34 270 top
C378  -  [C_0402NEW]  293.09 48.64 90 top
C379  -  [C_0402NEW]  289.78 52.2 90 top
C380  -  [C_0402NEW]  289.71 47.76 0 top
C381  -  [C_0402NEW]  276.19 46.1 90 top
C382  -  [C_0402NEW]  277.16 44.28 180 top
C383  -  [C_0402NEW]  277.16 45.16 180 top
C384  -  [C_0402NEW]  277.21 46.1 90 top
C398  -  [C_0402NEW]  241.22 57.23 180 top
C399  -  [C_0402NEW]  240.3 58.12 0 top
C400  -  [C_0402NEW]  243.25 50.88 180 top
C401  -  [C_0402NEW]  243.17 44.45 90 top
C405  -  [C_0402NEW]  241.52 51.69 90 top
C406  -  [C_0402NEW]  17.16 44.78 0 bottom
C407  -  [C_0402NEW]  19.98 46.05 180 top
C408  VAL  [C_0402-NV]  255.48 133.81 180 top
C414  VAL  [C_0402-NV]  257.01 133.81 180 top
C415  VAL  [C_0402-NV]  258.53 133.81 0 top
C416  -  [C_0402NEW]  181.12 194.01 0 top
C417  VAL  [C_0402-NV]  255.45 135.2 180 top
C418  -  [C_0402NEW]  181.5 196.32 0 top
C419  -  [C_0402NEW]  203.3 196.22 90 bottom
C420  VAL  [C_0402-NV]  256.98 135.2 180 top
C421  -  [C_0402NEW]  204.19 196.22 90 bottom
C422  -  [C_0402NEW]  202.41 196.22 90 bottom
C423  -  [C_0402NEW]  201.52 196.22 90 bottom
C424  -  [C_0402NEW]  200.12 194.21 90 bottom
C425  -  [C_0402NEW]  199.23 194.21 90 bottom
C426  -  [C_0402NEW]  108.94 94.01 270 top
C427  -  [C_0402NEW]  197.02 196.55 180 bottom
C428  -  [C_0402NEW]  196.11 197.44 0 bottom
C429  VAL  [C_0402-NV]  258.51 135.2 0 top
C430  VAL  [C_0402-NV]  260.03 135.2 0 top
C431  VAL  [C_0402-NV]  261.58 135.21 0 top
C432  VAL  [C_0402-NV]  261.58 136.6 0 top
C433  -  [C_0603NEW]  156.56 198.14 90 bottom
C434  -  [C_0402NEW]  157.65 199.31 270 bottom
C435  -  [C_0402NEW]  70.02 92.03 180 top
C436  -  [C_0402NEW]  67.03 87.58 180 top
C437  -  [C_0402NEW]  67.1 92.15 180 top
C438  -  [C_0402NEW]  69.36 87.58 0 top
C439  -  [C_0402NEW]  69.11 90.63 0 top
C448  -  [C_0402NEW]  72.18 92.92 180 bottom
C449  -  [C_0603NEW]  71.79 85.68 0 top
C450  -  [C_0402NEW]  66.97 89.11 180 top
C451  -  [C_0402NEW]  72.18 92.03 180 bottom
C452  -  [C_0402NEW]  72.18 91.14 180 bottom
C453  -  [C_0402NEW]  72.18 90.25 180 bottom
C454  -  [C_0402NEW]  72.18 89.36 180 bottom
C455  -  [C_0402NEW]  72.18 88.47 180 bottom
C456  -  [C_0402NEW]  72.18 87.58 180 bottom
C457  -  [C_0402NEW]  72.18 86.69 180 bottom
C460  -  [C_0402NEW]  75.28 85.09 90 bottom
C461  -  [C_0402NEW]  74.39 85.09 90 bottom
C463  -  [C_0603NEW]  14.89 165.31 0 top
C464  -  [C_0402NEW]  15.51 163.4 0 top
C465  -  [C_0402NEW]  16.4 164.27 180 top
C466  -  [C_0402NEW]  18.59 152.11 180 top
C467  -  [C_0402NEW]  18.59 153 180 top
C468  -  [C_0402NEW]  18.59 153.89 180 top
C469  -  [C_0402NEW]  18.59 154.78 180 top
C470  -  [C_0402NEW]  18.59 155.67 180 top
C471  -  [C_0402NEW]  18.59 156.56 180 top
C472  -  [C_0402NEW]  18.59 157.44 180 top
C473  -  [C_0402NEW]  18.59 158.33 180 top
C475  -  [C_0402NEW]  51.28 5.85 90 top
C476  -  [C_0402NEW]  50.39 6.76 270 top
C477  -  [C_0402NEW]  81.45 73.23 180 bottom
C478  -  [C_0402NEW]  81.45 71.45 180 bottom
C479  -  [C_0402NEW]  81.45 74.12 180 bottom
C480  -  [C_0402NEW]  81.45 75.01 180 bottom
C481  -  [C_0402NEW]  81.45 72.34 180 bottom
C482  -  [C_0402NEW]  81.45 68.79 180 bottom
C483  -  [C_0402NEW]  81.45 69.68 180 bottom
C484  -  [C_0402NEW]  81.45 70.56 180 bottom
C485  -  [C_0402NEW]  71.8 62.94 180 bottom
C486  -  [C_0402NEW]  71.8 61.17 180 bottom
C487  -  [C_0402NEW]  71.8 63.96 180 bottom
C488  -  [C_0402NEW]  71.8 64.85 180 bottom
C489  -  [C_0402NEW]  71.8 62.06 180 bottom
C490  -  [C_0402NEW]  71.8 58.5 180 bottom
C491  -  [C_0402NEW]  71.8 59.39 180 bottom
C492  -  [C_0402NEW]  71.8 60.28 180 bottom
C493  -  [C_0402NEW]  76.17 74.17 90 top
C494  -  [C_0402NEW]  16.23 69.88 270 top
C495  -  [C_0402NEW]  13.94 66.17 90 top
C496  -  [C_0402NEW]  76.42 70.01 270 top
C497  -  [C_0402NEW]  74.65 70.01 270 top
C500  -  [C_0402NEW]  21 30.43 180 top
C504  -  [C_0402NEW]  21 29.42 180 top
C505  -  [C_0402NEW]  56.41 41.1 0 bottom
C506  -  [C_0402NEW]  57.32 41.99 180 bottom
C507  -  [C_0402NEW]  63.22 61.12 270 top
C508  -  [C_0402NEW]  65.63 64.14 90 top
C509  -  [C_0402NEW]  106.4 2.04 90 top
C510  22U_0805_25V  [C_0805]  294.09 33.84 0 top
C511  22U_0805_25V  [C_0805]  294.09 32.13 0 top
C512  -  [C_0402NEW]  7.21 145.32 270 top
C514  -  [C_0402NEW]  63.98 64.14 90 top
C525  -  [C_0402NEW]  77.82 65.79 90 top
C526  -  [C_0402NEW]  73.63 75.09 270 top
C527  -  [C_0402NEW]  77.06 74.17 90 top
C528  -  [C_0402NEW]  73.63 70.01 270 top
C529  -  [C_0603NEW]  69.31 77.11 270 bottom
C530  -  [C_0402NEW]  75.15 78.9 270 bottom
C531  -  [C_0402NEW]  76.04 78.9 270 bottom
C537  -  [C_0402NEW]  69.44 55.5 90 bottom
C538  -  [C_0402NEW]  67.15 65.05 270 top
C539  -  [C_0402NEW]  68.04 61.37 270 top
C540  -  [C_0402NEW]  64.87 60.1 270 top
C541  -  [C_0402NEW]  13.18 143.03 270 bottom
C542  -  [C_0603NEW]  4.67 136.67 270 bottom
C543  -  [C_0402NEW]  6.7 135.77 90 bottom
C544  -  [C_0402NEW]  5.81 135.77 90 bottom
C545  -  [C_0805NEW]  249.05 74.76 0 top
C546  -  [C_0805NEW]  223.58 48.72 180 bottom
C547  -  [C_0805NEW]  224.09 48.72 180 top
C548  VAL  [C_0402-NV]  248 140.41 270 top
C549  -  [C_0402NEW]  279.12 68.28 90 bottom
C550  -  [C_0402NEW]  261.34 68.58 90 bottom
C551  -  [C_0402NEW]  280.89 68.28 90 bottom
C552  -  [C_0402NEW]  280 68.28 90 bottom
C553  -  [C_0603NEW]  279.56 70.69 180 top
C554  -  [C_0402NEW]  280.77 68.71 90 top
C555  -  [C_0402NEW]  284.96 60.07 90 top
C556  -  [C_0402NEW]  281.66 69.62 270 top
C557  -  [C_0402NEW]  285.85 60.07 90 top
C558  -  [C_0603NEW]  290.47 83.07 90 bottom
C559  -  [C_0603NEW]  290.42 81.68 270 bottom
C560  -  [C_0402NEW]  291.56 83.44 90 bottom
C561  -  [C_0402NEW]  292.45 81.56 270 bottom
C562  -  [C_0402NEW]  292.45 84.36 270 bottom
C563  -  [C_0402NEW]  291.56 80.65 90 bottom
C564  -  [C_0402NEW]  291.35 88.99 0 bottom
C565  -  [C_0402NEW]  277.9 66.25 0 top
C566  -  [C_0402NEW]  277.9 65.23 0 top
C567  -  [C_0402NEW]  277.9 64.21 0 top
C568  -  [C_0402NEW]  291.35 88.11 0 bottom
C569  -  [C_0402NEW]  291.33 86.61 0 bottom
C570  -  [C_0402NEW]  291.33 85.72 0 bottom
C571  -  [C_0402NEW]  277.9 63.2 0 top
C572  -  [C_0402NEW]  47.16 41.99 180 bottom
C573  -  [C_0603NEW]  60.29 67.58 270 top
C574  -  [C_0402NEW]  96.11 57.03 90 bottom
C575  -  [C_0402NEW]  95.09 61.62 270 bottom
C576  -  [C_0402NEW]  95.09 46.64 270 bottom
C577  -  [C_0402NEW]  95.09 40.01 90 bottom
C578  -  [C_0402NEW]  96.45 79.63 90 bottom
C579  -  [C_0402NEW]  96.45 84.23 270 bottom
C580  -  [C_0402NEW]  96.49 70.77 270 bottom
C581  -  [C_0402NEW]  96.45 64.52 90 bottom
C582  -  [C_0402NEW]  65.37 68.61 270 bottom
C583  -  [C_0402NEW]  66.26 68.61 270 bottom
C586  VAL  [C_0402-NV]  245.85 124.03 180 top
C587  VAL  [C_0402-NV]  252.32 124.03 0 top
C588  VAL  [C_0402-NV]  249.13 124.03 0 top
C589  VAL  [C_0402-NV]  256.26 140.08 0 top
C590  VAL  [C_0402-NV]  253.97 138 0 top
C591  VAL  [C_0402-NV]  255.5 138 180 top
C592  -  [C_0603NEW]  262.1 130.32 90 top
C593  -  [C_0603NEW]  255.75 131.72 270 top
C594  -  [C_0603NEW]  253.21 131.72 270 top
C595  -  [C_0603NEW]  246.86 130.32 90 top
C596  VAL  [C_0402-NV]  260.01 140.41 270 top
C597  VAL  [C_0402-NV]  263.11 133.05 180 top
C598  VAL  [C_0402-NV]  263.11 135.97 180 top
C599  -  [C_0402NEW]  78.02 98.12 180 bottom
C600  -  [C_1206]  25.81 39.7 0 top
C601  -  [C_0402NEW]  137.81 148.19 90 top
C602  -  [C_0402NEW]  25.8 37.8 0 top
C603  -  [C_0603NEW]  286.67 73.49 0 bottom
C604  -  [C_0603NEW]  286.67 74.76 0 bottom
C605  -  [C_0402NEW]  262.22 68.58 90 bottom
C606  -  [C_0402NEW]  260.45 68.58 90 bottom
C607  -  [C_0603NEW]  258.86 76.03 180 bottom
C608  -  [C_0603NEW]  258.86 74.76 180 bottom
C609  -  [C_0603NEW]  93.95 60.47 90 bottom
C610  -  [C_0603NEW]  94.97 58.06 270 bottom
C611  -  [C_0603NEW]  93.95 45.48 90 bottom
C612  -  [C_0603NEW]  93.95 41.42 270 bottom
C613  -  [C_0603NEW]  95.3 83.08 90 bottom
C614  -  [C_0603NEW]  95.3 80.92 270 bottom
C615  -  [C_0603NEW]  95.3 65.68 270 bottom
C616  -  [C_0603NEW]  95.3 69.74 90 bottom
C619  VAL  [C_0402-NV]  251.05 140.8 180 top
C620  VAL  [C_0402-NV]  253.94 140.41 270 top
C621  -  [C_0402NEW]  24.71 59.39 180 top
C622  -  [C_0402NEW]  48.43 34.88 180 bottom
C623  -  [C_0402NEW]  41.8 41.23 0 bottom
C624  -  [C_0805NEW]  18.38 34.71 270 top
C625  -  [C_0402NEW]  14.32 33.81 270 top
C626  -  [C_0402NEW]  80.74 97.45 270 top
C627  -  [C_0402NEW]  79.85 96.53 90 top
C628  -  [C_0402NEW]  268.57 11.71 270 top
C629  -  [C_0402NEW]  272.69 6.18 0 top
C630  -  [C_0402NEW]  203.88 112.47 180 bottom
C631  -  [C_0402NEW]  202.97 113.49 0 bottom
C632  -  [C_0603NEW]  201.44 111.52 90 bottom
C633  -  [C_0402NEW]  46.53 45.16 180 bottom
C634  -  [C_0402NEW]  206.04 116.28 180 bottom
C635  -  [C_0402NEW]  142.64 160.86 0 bottom
C636  -  [C_0402NEW]  207.94 116.28 180 bottom
C637  -  [C_0603NEW]  291.75 75.14 180 bottom
C638  -  [C_0402NEW]  206.98 119.51 90 top
C639  -  [C_0603NEW]  97.44 93.04 0 bottom
C640  -  [C_0402NEW]  72.99 20.45 90 top
C641  -  [C_0402NEW]  278.28 26.11 0 bottom
C642  -  [C_0402NEW]  279.19 27 180 bottom
C643  -  [C_0402NEW]  276.78 20.7 180 top
C644  -  [C_0402NEW]  273.32 20.7 0 top
C648  -  [C_0402NEW]  24.71 60.41 180 top
C650  -  [C_0402NEW]  222.68 129.87 180 top
C653  -  [C_0402NEW]  222.68 133.18 180 top
C654  -  [C_0402NEW]  222.68 132.29 180 top
C655  VAL  [C_0402-NV]  242.23 137.37 180 top
C656  VAL  [C_0402-NV]  241.9 135.21 180 top
C657  VAL  [C_0402-NV]  244.06 137.37 0 top
C658  VAL  [C_0402-NV]  244.16 136.43 0 top
